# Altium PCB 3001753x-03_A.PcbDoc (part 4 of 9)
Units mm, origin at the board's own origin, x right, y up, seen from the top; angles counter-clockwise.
Board outline 210 x 130 mm, 8 copper layers (1-TOP, 2-GND, 3-INTOP, 4-PWR, 5-PWR, 6-INBOT, 7-GND, 8-BOTTOM), stack 1.646 mm thick; 676 components, 623 nets, 2861 pads, 2382 vias.
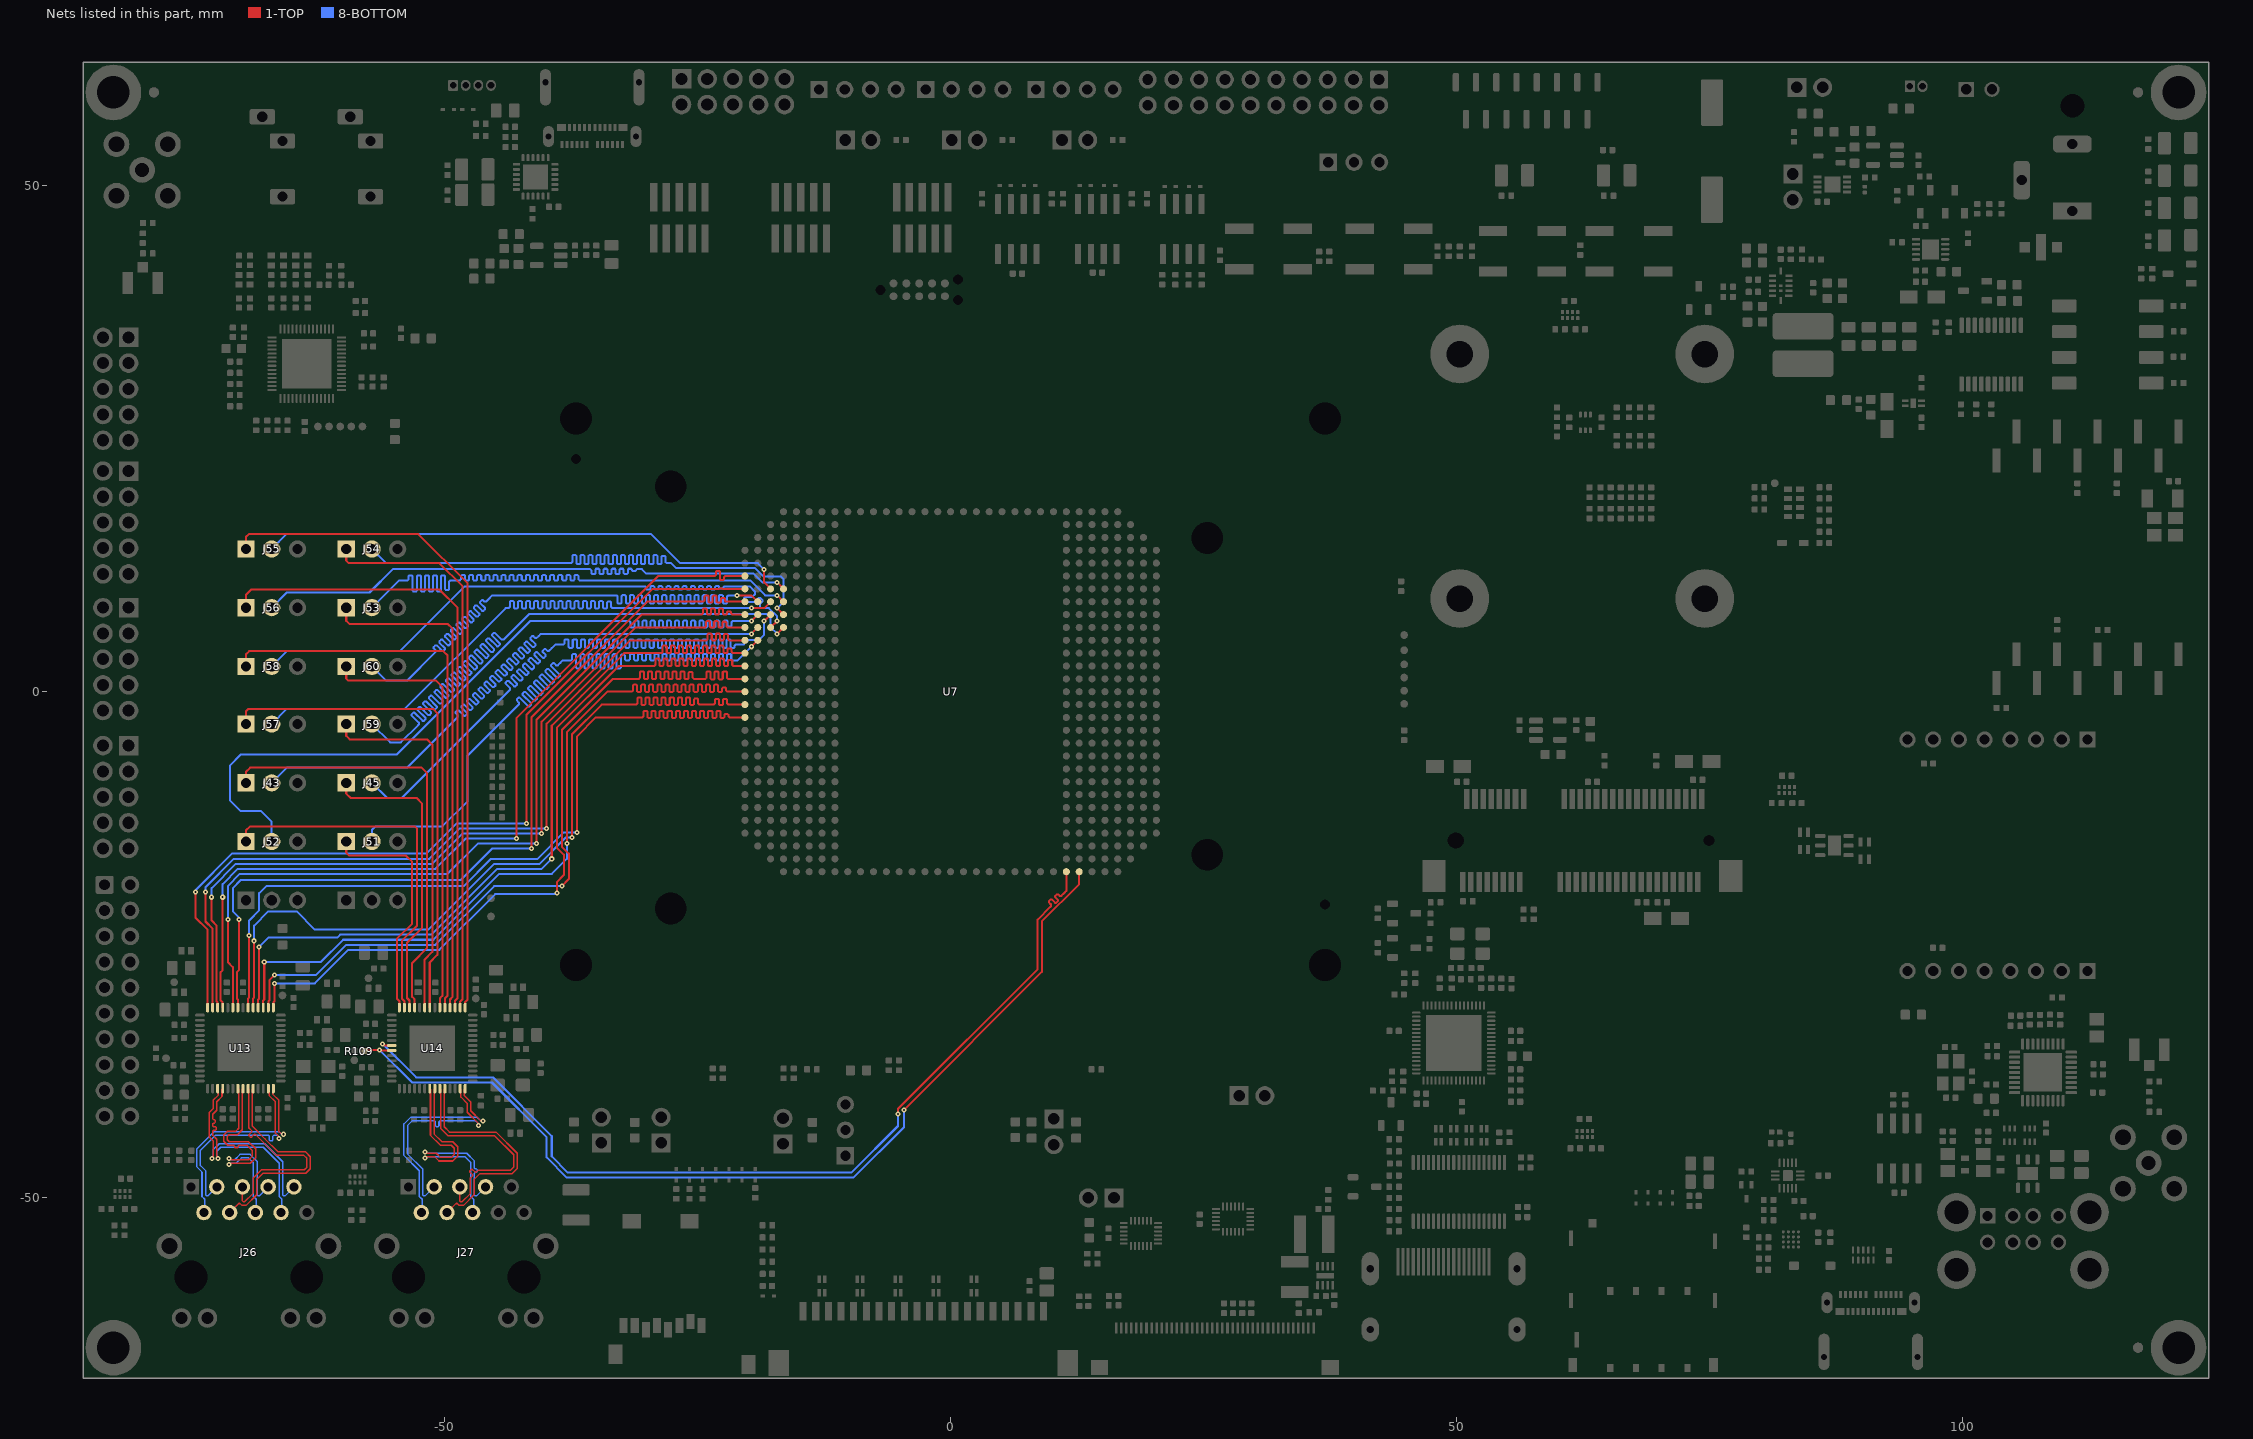
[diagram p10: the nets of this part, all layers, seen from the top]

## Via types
v1: diameter 0.5, hole 0.2, 1-TOP to 8-BOTTOM, 1547 vias
v2: diameter 0.68, hole 0.3, 1-TOP to 8-BOTTOM, 835 vias

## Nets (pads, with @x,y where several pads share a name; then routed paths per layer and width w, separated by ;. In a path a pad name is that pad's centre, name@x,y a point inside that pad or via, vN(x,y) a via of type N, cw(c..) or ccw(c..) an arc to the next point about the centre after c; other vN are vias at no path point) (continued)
ENET1_RD0: U7.A16 U13.44 | length 85
  1-TOP w0.2: U13.44@-67.4,-31.2 -67.4,-30.6 -67.3,-30.5 -67.3,-28.5 v1(-66.8,-28) ; v1(-38.4,-19.2) -37.7,-18.5 -37.7,-16 -38.4,-15.3 -38.4,-3.779 -33.351,1.27 -30.898,1.27 -30.798,1.27 -30.681,1.387 -30.681,1.927 -30.601,2.007 -30.361,2.007 -30.281,1.927 -30.281,1.315 -30.201,1.235 -29.961,1.235 -29.881,1.315 -29.881,1.927 -29.801,2.007 -29.561,2.007 -29.481,1.927 -29.481,1.315 -29.401,1.235 -29.161,1.235 -29.081,1.315 -29.081,1.927 -29.001,2.007 -28.761,2.007 -28.681,1.927 -28.681,1.315 -28.601,1.235 -28.361,1.235 -28.281,1.315 -28.281,1.927 -28.201,2.007 -27.961,2.007 -27.881,1.927 -27.881,1.315 -27.801,1.235 -27.561,1.235 -27.481,1.315 -27.481,1.927 -27.401,2.007 -27.161,2.007 -27.081,1.927 -27.081,1.315 -27.001,1.235 -26.761,1.235 -26.681,1.315 -26.681,1.927 -26.601,2.007 -26.361,2.007 -26.281,1.927 -26.281,1.315 -26.201,1.235 -25.961,1.235 -25.881,1.315 -25.881,1.871 -25.801,1.951 -25.561,1.951 -25.481,1.871 -25.481,1.387 -25.364,1.27 -24.8,1.27 -24.325,1.27 -24.225,1.27 -24.108,1.387 -24.108,1.937 -24.028,2.017 -23.788,2.017 -23.708,1.937 -23.708,1.301 -23.628,1.221 -23.388,1.221 -23.308,1.301 -23.308,1.937 -23.228,2.017 -22.988,2.017 -22.908,1.937 -22.908,1.301 -22.828,1.221 -22.588,1.221 -22.508,1.301 -22.508,1.937 -22.428,2.017 -22.188,2.017 -22.108,1.937 -22.108,1.387 -21.991,1.27 -21.375,1.27 U7.A16@-20.32,1.27
  8-BOTTOM w0.2: v1(-66.8,-28) -62.7,-28 -59.7,-25 -50.9,-25 -45.1,-19.2 v1(-38.4,-19.2)
ENET1_RD1: U7.A15 U13.45 | length 85
  1-TOP w0.2: U13.45@-67.9,-31.2 -67.9,-30.5 -67.8,-30.4 v1(-67.8,-26.7) ; v1(-37.9,-15) -37.9,-3.986 -33.914,0 -31.594,0 -31.494,0 -31.377,0.117 -31.377,0.628 -31.297,0.708 -31.057,0.708 -30.977,0.628 -30.977,0.057 -30.897,-0.023 -30.657,-0.023 -30.577,0.057 -30.577,0.628 -30.497,0.708 -30.257,0.708 -30.177,0.628 -30.177,0.057 -30.097,-0.023 -29.857,-0.023 -29.777,0.057 -29.777,0.628 -29.697,0.708 -29.457,0.708 -29.377,0.628 -29.377,0.057 -29.297,-0.023 -29.057,-0.023 -28.977,0.057 -28.977,0.628 -28.897,0.708 -28.657,0.708 -28.577,0.628 -28.577,0.057 -28.497,-0.023 -28.257,-0.023 -28.177,0.057 -28.177,0.628 -28.097,0.708 -27.857,0.708 -27.777,0.628 -27.777,0.057 -27.697,-0.023 -27.457,-0.023 -27.377,0.057 -27.377,0.628 -27.297,0.708 -27.057,0.708 -26.977,0.628 -26.977,0.057 -26.897,-0.023 -26.657,-0.023 -26.577,0.057 -26.577,0.628 -26.497,0.708 -26.257,0.708 -26.177,0.628 -26.177,0.057 -26.097,-0.023 -25.857,-0.023 -25.777,0.057 -25.777,0.628 -25.697,0.708 -25.457,0.708 -25.377,0.628 -25.377,0.057 -25.297,-0.023 -25.057,-0.023 -24.977,0.057 -24.977,0.628 -24.897,0.708 -24.657,0.708 -24.577,0.628 -24.577,0.057 -24.497,-0.023 -24.257,-0.023 -24.177,0.057 -24.177,0.628 -24.097,0.708 -23.857,0.708 -23.777,0.628 -23.777,0.057 -23.697,-0.023 -23.457,-0.023 -23.377,0.057 -23.377,0.628 -23.297,0.708 -23.057,0.708 -22.977,0.628 -22.977,0.057 -22.897,-0.023 -22.657,-0.023 -22.577,0.057 -22.577,0.33 -22.497,0.41 -22.257,0.41 -22.177,0.33 -22.177,0.117 -22.06,0 -21.638,0 U7.A15@-20.32,0
  8-BOTTOM w0.2: v1(-67.8,-26.7) -62.2,-26.7 -60,-24.5 -51.1,-24.5 -44.6,-18 -39.4,-18 -37.9,-16.5 v1(-37.9,-15)
ENET1_RD2: U7.A14 U13.47 | length 85
  1-TOP w0.2: U13.47@-68.9,-31.2 -68.9,-30.3 -68.8,-30.2 v1(-68.8,-24.6) ; v1(-37.4,-14.4) -37.4,-4.193 -34.477,-1.27 -31.162,-1.27 -31.062,-1.27 -30.944,-1.153 -30.944,-0.638 -30.864,-0.558 -30.624,-0.558 -30.544,-0.638 -30.544,-1.212 -30.464,-1.292 -30.224,-1.292 -30.144,-1.212 -30.144,-0.638 -30.064,-0.558 -29.824,-0.558 -29.744,-0.638 -29.744,-1.212 -29.664,-1.292 -29.425,-1.292 -29.345,-1.212 -29.345,-0.638 -29.265,-0.558 -29.025,-0.558 -28.945,-0.638 -28.945,-1.212 -28.865,-1.292 -28.625,-1.292 -28.545,-1.212 -28.545,-0.638 -28.465,-0.558 -28.225,-0.558 -28.145,-0.638 -28.145,-1.212 -28.065,-1.292 -27.825,-1.292 -27.745,-1.212 -27.745,-0.638 -27.665,-0.558 -27.425,-0.558 -27.345,-0.638 -27.345,-1.212 -27.265,-1.292 -27.025,-1.292 -26.945,-1.212 -26.945,-0.638 -26.865,-0.558 -26.625,-0.558 -26.545,-0.638 -26.545,-1.212 -26.465,-1.292 -26.225,-1.292 -26.145,-1.212 -26.145,-0.638 -26.065,-0.558 -25.825,-0.558 -25.745,-0.638 -25.745,-1.212 -25.665,-1.292 -25.425,-1.292 -25.345,-1.212 -25.345,-0.749 -25.265,-0.669 -25.025,-0.669 -24.945,-0.749 -24.945,-1.153 -24.827,-1.27 -24.176,-1.27 -23.506,-1.27 -23.406,-1.27 -23.289,-1.153 -23.289,-0.788 -23.209,-0.708 -22.969,-0.708 -22.889,-0.788 -22.889,-1.238 -22.809,-1.318 -22.569,-1.318 -22.489,-1.238 -22.489,-0.788 -22.409,-0.708 -22.169,-0.708 -22.089,-0.788 -22.089,-1.153 -21.971,-1.27 -21.325,-1.27 U7.A14@-20.32,-1.27
  8-BOTTOM w0.2: v1(-68.8,-24.6) -68.8,-23.1 -67.4,-21.7 -64.6,-21.7 -62.8,-23.5 -51.6,-23.5 -45.1,-17 -40.6,-17 -38,-14.4 v1(-37.4,-14.4)
ENET1_RD3: U7.A13 U13.48 | length 85
  1-TOP w0.2: U13.48@-69.4,-31.2 -69.4,-30.3 -69.3,-30.2 v1(-69.3,-24.1) ; v1(-36.9,-13.9) -36.9,-4.4 -35.04,-2.54 -30.561,-2.54 -30.461,-2.54 -30.343,-2.423 -30.343,-1.963 -30.263,-1.883 -30.023,-1.883 -29.943,-1.963 -29.943,-2.501 -29.863,-2.581 -29.623,-2.581 -29.543,-2.501 -29.543,-1.963 -29.463,-1.883 -29.223,-1.883 -29.143,-1.963 -29.143,-2.501 -29.063,-2.581 -28.823,-2.581 -28.743,-2.501 -28.743,-1.963 -28.663,-1.883 -28.423,-1.883 -28.343,-1.963 -28.343,-2.501 -28.263,-2.581 -28.023,-2.581 -27.943,-2.501 -27.943,-1.963 -27.863,-1.883 -27.623,-1.883 -27.543,-1.963 -27.543,-2.501 -27.463,-2.581 -27.223,-2.581 -27.143,-2.501 -27.143,-1.963 -27.063,-1.883 -26.823,-1.883 -26.743,-1.963 -26.743,-2.501 -26.663,-2.581 -26.423,-2.581 -26.343,-2.501 -26.343,-1.963 -26.263,-1.883 -26.023,-1.883 -25.943,-1.963 -25.943,-2.501 -25.863,-2.581 -25.623,-2.581 -25.543,-2.501 -25.543,-1.963 -25.463,-1.883 -25.223,-1.883 -25.143,-1.963 -25.143,-2.501 -25.063,-2.581 -24.823,-2.581 -24.743,-2.501 -24.743,-1.963 -24.663,-1.883 -24.423,-1.883 -24.343,-1.963 -24.343,-2.501 -24.263,-2.581 -24.023,-2.581 -23.943,-2.501 -23.943,-1.963 -23.863,-1.883 -23.623,-1.883 -23.543,-1.963 -23.543,-2.501 -23.463,-2.581 -23.223,-2.581 -23.143,-2.501 -23.143,-1.963 -23.063,-1.883 -22.823,-1.883 -22.743,-1.963 -22.743,-2.501 -22.663,-2.581 -22.423,-2.581 -22.343,-2.501 -22.343,-2.295 -22.263,-2.215 -22.023,-2.215 -21.943,-2.295 -21.943,-2.423 -21.826,-2.54 -21.55,-2.54 U7.A13@-20.32,-2.54
  8-BOTTOM w0.2: v1(-69.3,-24.1) -69.3,-22.6 -68.3,-21.6 -68.3,-19.9 -67.6,-19.2 -48.1,-19.2 -45.4,-16.5 -40.8,-16.5 -38.2,-13.9 v1(-36.9,-13.9)
ENET1_RX_CTL: U7.A17 U13.43 | length 85
  1-TOP w0.2: U13.43@-66.9,-31.2 -66.9,-30.7 -66.8,-30.6 v1(-66.8,-28.8) ; v1(-38.9,-19.9) -38.9,-18.8 -38.2,-18.1 -38.2,-16.1 -38.9,-15.4 -38.9,-3.572 -32.788,2.54 -29.386,2.54 -29.286,2.54 -29.169,2.657 -29.169,3.217 -29.089,3.297 -28.849,3.297 -28.769,3.217 -28.769,2.617 -28.689,2.537 -28.449,2.537 -28.369,2.617 -28.369,3.217 -28.289,3.297 -28.049,3.297 -27.969,3.217 -27.969,2.617 -27.889,2.537 -27.649,2.537 -27.569,2.617 -27.569,3.217 -27.489,3.297 -27.249,3.297 -27.169,3.217 -27.169,2.617 -27.089,2.537 -26.849,2.537 -26.769,2.617 -26.769,3.217 -26.689,3.297 -26.449,3.297 -26.369,3.217 -26.369,2.617 -26.289,2.537 -26.049,2.537 -25.969,2.617 -25.969,3.217 -25.889,3.297 -25.649,3.297 -25.569,3.217 -25.569,2.617 -25.489,2.537 -25.249,2.537 -25.169,2.617 -25.169,3.217 -25.089,3.297 -24.849,3.297 -24.769,3.217 -24.769,2.617 -24.689,2.537 -24.449,2.537 -24.369,2.617 -24.369,3.217 -24.289,3.297 -24.049,3.297 -23.969,3.217 -23.969,2.617 -23.889,2.537 -23.649,2.537 -23.569,2.617 -23.569,3.217 -23.489,3.297 -23.249,3.297 -23.169,3.217 -23.169,2.617 -23.089,2.537 -22.849,2.537 -22.769,2.617 -22.769,3.217 -22.689,3.297 -22.449,3.297 -22.369,3.217 -22.369,2.617 -22.289,2.537 -22.049,2.537 -21.969,2.617 -21.969,3.064 -21.889,3.144 -21.649,3.144 -21.569,3.064 -21.569,2.657 -21.452,2.54 -20.972,2.54 U7.A17@-20.32,2.54
  8-BOTTOM w0.2: v1(-66.8,-28.8) -62.8,-28.8 -59.5,-25.5 -50.5,-25.5 -45,-20 -39.167,-20 -39.125,-19.957 -38.957,-19.957 v1(-38.9,-19.9)
ENET1_RXC: U7.A18 U13.46 | length 85
  1-TOP w0.2: U13.46@-68.4,-31.2 -68.4,-30.4 -68.3,-30.3 v1(-68.3,-25.2) ; v1(-39.4,-16.5) -39.4,-3.35 -36.44,-0.39 -32.24,3.81 -28.656,3.81 -28.556,3.81 -28.439,3.927 -28.439,4.477 -28.359,4.557 -28.119,4.557 -28.039,4.477 -28.039,3.885 -27.959,3.805 -27.719,3.805 -27.639,3.885 -27.639,4.477 -27.559,4.557 -27.319,4.557 -27.239,4.477 -27.239,3.885 -27.159,3.805 -26.919,3.805 -26.839,3.885 -26.839,4.477 -26.759,4.557 -26.519,4.557 -26.439,4.477 -26.439,3.885 -26.359,3.805 -26.119,3.805 -26.039,3.885 -26.039,4.477 -25.959,4.557 -25.719,4.557 -25.639,4.477 -25.639,3.885 -25.559,3.805 -25.319,3.805 -25.239,3.885 -25.239,4.477 -25.159,4.557 -24.919,4.557 -24.839,4.477 -24.839,3.885 -24.759,3.805 -24.519,3.805 -24.439,3.885 -24.439,4.477 -24.359,4.557 -24.119,4.557 -24.039,4.477 -24.039,3.885 -23.959,3.805 -23.719,3.805 -23.639,3.885 -23.639,4.477 -23.559,4.557 -23.319,4.557 -23.239,4.477 -23.239,3.885 -23.159,3.805 -22.919,3.805 -22.839,3.885 -22.839,4.477 -22.759,4.557 -22.519,4.557 -22.439,4.477 -22.439,3.885 -22.359,3.805 -22.119,3.805 -22.039,3.885 -22.039,4.208 -21.959,4.288 -21.719,4.288 -21.639,4.208 -21.639,3.927 -21.522,3.81 -21.2,3.81 -21.1,3.81 U7.A18@-20.32,3.81
  8-BOTTOM w0.2: v1(-68.3,-25.2) -67.4,-24.3 -60.6,-24.3 -60.3,-24 -51.3,-24 -44.8,-17.5 -40.4,-17.5 v1(-39.4,-16.5)
ENET1_TD0: U7.A22 U13.50 | length 85
  1-TOP w0.2: U13.50@-70.4,-31.2 -70.4,-30.4 -70.5,-30.3 -70.5,-27.7 -70.3,-27.5 v1(-70.3,-22.5) ; v1(-41.4,-15.5) -41.4,-2.536 -29.974,8.89 -24.52,8.89 -24.42,8.89 -24.303,9.007 -24.303,9.419 -24.223,9.499 -23.983,9.499 -23.903,9.419 -23.903,8.878 -23.823,8.798 -23.583,8.798 -23.503,8.878 -23.503,9.419 -23.423,9.499 -23.183,9.499 -23.103,9.419 -23.103,8.878 -23.023,8.798 -22.783,8.798 -22.703,8.878 -22.703,9.188 -22.623,9.268 -22.383,9.268 -22.303,9.188 -22.303,9.007 -22.185,8.89 -21.7,8.89 U7.A22@-20.32,8.89
  8-BOTTOM w0.2: v1(-70.3,-22.5) -70.357,-22.443 -70.357,-22.243 -70.9,-21.7 -70.9,-19.4 -70.1,-18.6 -48.4,-18.6 -45.3,-15.5 v1(-41.4,-15.5)
ENET1_TD1: U7.A21 U13.51 | length 85
  1-TOP w0.2: v1(-71.4,-22.5) -71.4,-26.7 -70.9,-27.2 U13.51@-70.9,-31.2 ; v1(-40.9,-15) -40.9,-2.743 -37.057,1.1 -30.537,7.62 -24.699,7.62 -24.599,7.62 -24.482,7.737 -24.482,8.125 -24.402,8.205 -24.162,8.205 -24.082,8.125 -24.082,7.69 -24.002,7.61 -23.762,7.61 -23.682,7.69 -23.682,8.125 -23.602,8.205 -23.362,8.205 -23.282,8.125 -23.282,7.69 -23.202,7.61 -22.962,7.61 -22.882,7.69 -22.882,8.125 -22.802,8.205 -22.562,8.205 -22.482,8.125 -22.482,7.69 -22.402,7.61 -22.162,7.61 -22.082,7.69 -22.082,7.864 -22.002,7.944 -21.762,7.944 -21.682,7.864 -21.682,7.737 -21.565,7.62 -21.375,7.62 U7.A21@-20.32,7.62
  8-BOTTOM w0.2: v1(-71.4,-22.5) -71.4,-19.2 -70.2,-18 -49.7,-18 -46.7,-15 v1(-40.9,-15)
ENET1_TD2: U7.A20 U13.54 | length 85
  1-TOP w0.2: v1(-73,-20.3) -73,-22.6 -72.5,-23.1 -72.5,-30.6 -72.4,-30.7 U13.54@-72.4,-31.2 ; v1(-40.4,-14) -40.4,-2.95 -36.85,0.6 -31.1,6.35 -24.365,6.35 -24.265,6.35 -24.147,6.467 -24.147,6.901 -24.067,6.981 -23.827,6.981 -23.747,6.901 -23.747,6.407 -23.667,6.327 -23.427,6.327 -23.347,6.407 -23.347,6.901 -23.267,6.981 -23.027,6.981 -22.947,6.901 -22.947,6.407 -22.867,6.327 -22.627,6.327 -22.547,6.407 -22.547,6.833 -22.467,6.913 -22.227,6.913 -22.147,6.833 -22.147,6.467 -22.03,6.35 -21.375,6.35 U7.A20@-20.32,6.35
  8-BOTTOM w0.2: v1(-73,-20.3) -73,-19.4 -70.6,-17 -51.2,-17 -48.2,-14 v1(-40.4,-14)
ENET1_TD3: U7.A19 U13.55 | length 85
  1-TOP w0.2: v1(-73.6,-19.8) -73.6,-22.7 -72.9,-23.4 U13.55@-72.9,-31.2 ; v1(-39.9,-13.5) -39.9,-3.157 -36.643,0.1 -31.663,5.08 -24.211,5.08 -24.111,5.08 -23.994,5.197 -23.994,5.668 -23.914,5.748 -23.674,5.748 -23.594,5.668 -23.594,5.141 -23.514,5.061 -23.274,5.061 -23.194,5.141 -23.194,5.668 -23.114,5.748 -22.874,5.748 -22.794,5.668 -22.794,5.141 -22.714,5.061 -22.474,5.061 -22.394,5.141 -22.394,5.616 -22.314,5.696 -22.074,5.696 -21.994,5.616 -21.994,5.197 -21.877,5.08 -21.293,5.08 U7.A19@-20.32,5.08
  8-BOTTOM w0.2: v1(-73.6,-19.8) -73.6,-19.3 -70.8,-16.5 -51.5,-16.5 -48.5,-13.5 v1(-39.9,-13.5)
ENET1_TX_CTL: U7.A23 U13.56 | length 85
  1-TOP w0.2: v1(-74.6,-19.8) -74.6,-22.3 -73.4,-23.5 U13.56@-73.4,-31.2 ; v1(-41.9,-13) -41.9,-2.3 -29.44,10.16 -22.875,10.16 -22.825,10.21 -22.55,10.21 -22.5,10.16 U7.A23@-20.32,10.16
  8-BOTTOM w0.2: v1(-74.6,-19.8) -74.543,-19.743 -74.543,-19.543 -71,-16 -51.8,-16 -48.8,-13 v1(-41.9,-13)
ENET1_TXC: U7.A24 U13.53 | length 85
  1-TOP w0.2: U13.53@-71.9,-31.2 -71.9,-30.7 -72.1,-30.5 -72.1,-27.7 -71.9,-27.5 v1(-71.9,-20.3) ; v1(-42.9,-14.5) -42.9,-2.6 -28.87,11.43 -23.394,11.43 -23.294,11.43 -23.177,11.547 -23.177,11.85 -23.097,11.93 -22.857,11.93 -22.777,11.85 -22.777,11.107 -22.697,11.027 -22.457,11.027 -22.377,11.107 -22.377,11.313 -22.259,11.43 -21.559,11.43 U7.A24@-20.32,11.43
  8-BOTTOM w0.2: v1(-71.9,-20.3) -71.9,-19 -70.4,-17.5 -50.9,-17.5 -47.9,-14.5 v1(-42.9,-14.5)
ENET2_MDC: U7.AF1 U14.7 | length 93.9
  1-TOP w0.2: v1(-56.1,-34.8) -55.95,-34.95 U14.7@-55.2,-34.95 ; v1(-5.2,-41.7) -5.2,-41.2 8.595,-27.405 8.595,-22.505 9.849,-21.251 9.919,-21.181 9.919,-21.015 9.705,-20.801 9.705,-20.688 9.875,-20.518 9.988,-20.518 10.316,-20.846 10.429,-20.846 10.599,-20.677 10.599,-20.563 10.331,-20.295 10.331,-20.182 10.501,-20.012 10.614,-20.012 10.768,-20.166 10.934,-20.166 11.2,-19.9 11.43,-19.67 U7.AF1@11.43,-17.78
  8-BOTTOM w0.2: v1(-56.1,-34.8) -52.8,-38.1 -45.2,-38.1 -39.4,-43.9 -39.4,-45.9 -37.8,-47.5 -9.8,-47.5 -5.2,-42.9 v1(-5.2,-41.7)
ENET2_MDIO: R109.2 U7.AG1 U14.8 | length 95.4
  1-TOP w0.2: R109.2@-57.92,-35.5 -57.82,-35.4 v1(-56.4,-35.4) -56.35,-35.45 U14.8@-55.2,-35.45 ; v1(-4.6,-41.3) 9.019,-27.681 9.019,-22.681 12.7,-19 U7.AG1@12.7,-17.78
  8-BOTTOM w0.2: v1(-56.4,-35.4) -53.2,-38.6 -45.3,-38.6 -39.9,-44 -39.9,-46 -37.9,-48 -9.6,-48 -4.6,-43 v1(-4.6,-41.3)
ENET2_RD0: J54.1 U14.44 | length 55.4
  1-TOP w0.2: J54.1@-59.7,14.1 -59.7,12.94 -59.46,12.7 -50.5,12.7 -48.2,10.4 -48.2,-30.35 -48.45,-30.6 U14.44@-48.45,-31.2
ENET2_RD0/UART4_RX: J54.2 U7.D21 | length 64.7
  1-TOP w0.2: v1(-17.145,8.255) U7.D21@-16.51,7.62
  8-BOTTOM w0.2: J54.2@-57.16,14.1 -55.76,12.7 -37.588,12.7 -37.488,12.7 -37.371,12.817 -37.371,13.42 -37.291,13.5 -37.051,13.5 -36.971,13.42 -36.971,12.686 -36.891,12.606 -36.651,12.606 -36.571,12.686 -36.571,13.42 -36.491,13.5 -36.251,13.5 -36.171,13.42 -36.171,12.686 -36.091,12.606 -35.851,12.606 -35.771,12.686 -35.771,13.42 -35.691,13.5 -35.451,13.5 -35.371,13.42 -35.371,12.686 -35.291,12.606 -35.051,12.606 -34.971,12.686 -34.971,13.42 -34.891,13.5 -34.651,13.5 -34.571,13.42 -34.571,12.686 -34.491,12.606 -34.251,12.606 -34.171,12.686 -34.171,13.42 -34.091,13.5 -33.851,13.5 -33.771,13.42 -33.771,12.686 -33.691,12.606 -33.451,12.606 -33.371,12.686 -33.371,13.42 -33.291,13.5 -33.051,13.5 -32.971,13.42 -32.971,12.686 -32.891,12.606 -32.651,12.606 -32.571,12.686 -32.571,13.42 -32.491,13.5 -32.251,13.5 -32.171,13.42 -32.171,12.686 -32.091,12.606 -31.851,12.606 -31.771,12.686 -31.771,13.42 -31.691,13.5 -31.451,13.5 -31.371,13.42 -31.371,12.686 -31.291,12.606 -31.051,12.606 -30.971,12.686 -30.971,13.42 -30.891,13.5 -30.651,13.5 -30.571,13.42 -30.571,12.686 -30.491,12.606 -30.251,12.606 -30.171,12.686 -30.171,13.42 -30.091,13.5 -29.851,13.5 -29.771,13.42 -29.771,12.686 -29.691,12.606 -29.451,12.606 -29.371,12.686 -29.371,13.42 -29.291,13.5 -29.051,13.5 -28.971,13.42 -28.971,12.686 -28.891,12.606 -28.651,12.606 -28.571,12.686 -28.571,13.346 -28.491,13.426 -28.251,13.426 -28.171,13.346 -28.171,12.817 -28.054,12.7 -27.71,12.7 -27.6,12.7 -27.1,12.2 -19.3,12.2 -18.5,11.4 -16.8,11.4 -16.5,11.1 -16.5,8.9 v1(-17.145,8.255)
ENET2_RD1: J56.1 U14.45 | length 62.8
  1-TOP w0.2: J56.1@-69.6,8.3 -69.6,9.6 -69.1,10.1 -50.5,10.1 -48.7,8.3 -48.7,-30.25 -48.95,-30.5 U14.45@-48.95,-31.2
ENET2_RD1/GPIO4_IO25: J56.2 U7.D23 | length 57.4
  1-TOP w0.2: v1(-17.145,10.795) U7.D23@-16.51,10.16
  8-BOTTOM w0.2: J56.2@-67.06,8.3 -65.56,9.8 -57.4,9.8 -55.1,12.1 -36.107,12.1 -35.607,12.1 -35.49,11.983 -35.49,11.695 -35.41,11.615 -35.17,11.615 -35.09,11.695 -35.09,12.067 -35.01,12.147 -34.77,12.147 -34.69,12.067 -34.69,11.695 -34.61,11.615 -34.37,11.615 -34.29,11.695 -34.29,12.067 -34.21,12.147 -33.97,12.147 -33.89,12.067 -33.89,11.695 -33.81,11.615 -33.57,11.615 -33.49,11.695 -33.49,12.067 -33.41,12.147 -33.17,12.147 -33.09,12.067 -33.09,11.695 -33.01,11.615 -32.77,11.615 -32.69,11.695 -32.69,12.067 -32.61,12.147 -32.37,12.147 -32.29,12.067 -32.29,11.722 -32.21,11.642 -31.97,11.642 -31.89,11.722 -31.89,12.067 -31.81,12.147 -31.57,12.147 -31.49,12.067 -31.49,11.983 -31.41,11.903 -31.17,11.903 -31.09,11.983 -30.973,12.1 -30.592,12.1 -30.5,12.1 -30.1,11.7 -19.5,11.7 -18.595,10.795 v1(-17.145,10.795)
ENET2_RD2: J58.1 U14.47 | length 56.3
  1-TOP w0.2: J58.1@-69.6,2.5 -69.6,3.7 -69.3,4 -50.1,4 -49.7,3.6 -49.7,-30.05 -49.95,-30.3 U14.47@-49.95,-31.2
ENET2_RD2/UART4_CTS: J58.2 U7.C20 | length 63.9
  1-TOP w0.2: U7.C20@-17.78,6.35 v1(-17.145,6.985)
  8-BOTTOM w0.2: J58.2@-67.06,2.5 -65.56,4 -54.4,4 -48,10.4 -30.685,10.4 -30.185,10.4 -30.068,10.283 -30.068,10.172 -29.988,10.092 -29.748,10.092 -29.668,10.172 -29.668,10.35 -29.588,10.43 -29.348,10.43 -29.268,10.35 -29.268,10.172 -29.188,10.092 -28.948,10.092 -28.868,10.172 -28.868,10.35 -28.788,10.43 -28.548,10.43 -28.468,10.35 -28.468,10.172 -28.388,10.092 -28.148,10.092 -28.068,10.172 -28.068,10.35 -27.988,10.43 -27.748,10.43 -27.668,10.35 -27.668,10.172 -27.588,10.092 -27.348,10.092 -27.268,10.172 -27.268,10.35 -27.188,10.43 -26.948,10.43 -26.868,10.35 -26.868,10.172 -26.788,10.092 -26.548,10.092 -26.468,10.172 -26.468,10.35 -26.388,10.43 -26.148,10.43 -26.068,10.35 -26.068,10.172 -25.988,10.092 -25.748,10.092 -25.668,10.172 -25.668,10.35 -25.588,10.43 -25.348,10.43 -25.268,10.35 -25.268,10.172 -25.188,10.092 -24.948,10.092 -24.868,10.172 -24.868,10.35 -24.788,10.43 -24.548,10.43 -24.468,10.35 -24.468,10.172 -24.388,10.092 -24.148,10.092 -24.068,10.172 -24.068,10.35 -23.988,10.43 -23.748,10.43 -23.668,10.35 -23.668,10.173 -23.588,10.093 -23.348,10.093 -23.268,10.173 -23.268,10.35 -23.188,10.43 -22.948,10.43 -22.868,10.35 -22.868,10.283 -22.788,10.203 -22.548,10.203 -22.468,10.283 ; -22.468,10.283 -22.351,10.4 -21.975,10.4 -19.85,10.4 -19.325,9.875 -19.325,9.625 -19.575,9.375 -20.3,9.375 -20.425,9.25 -20.425,9.025 -20.275,8.875 -19.375,8.875 -19,9.25 -18.775,9.25 -18.6,9.075 -18.6,8.9 -18.85,8.65 -18.85,8.375 -18.725,8.25 -17.95,8.25 -17.145,7.445 v1(-17.145,6.985)
ENET2_RD3: J60.1 U14.48 | length 42.8
  1-TOP w0.2: J60.1@-59.7,2.5 -59.7,1.3 -59.5,1.1 -50.825,1.1 -50.2,0.475 -50.2,-30.05 -50.45,-30.3 U14.48@-50.45,-31.2
ENET2_RD3/GPIO4_IO27: J60.2 U7.B22 | length 77.3
  1-TOP w0.2: v1(-21.1,9.525) -19.685,9.525 U7.B22@-19.05,8.89
  8-BOTTOM w0.2: J60.2@-57.16,2.5 -55.76,1.1 -53.7,1.1 -50.938,3.862 -50.868,3.932 -50.868,4.098 -51.062,4.292 -51.062,4.405 -50.892,4.575 -50.779,4.575 -50.23,4.026 -50.116,4.026 -49.947,4.196 -49.947,4.309 -50.496,4.858 -50.496,4.971 -50.326,5.141 -50.213,5.141 -49.664,4.591 -49.551,4.591 -49.381,4.761 -49.381,4.874 -49.93,5.424 -49.93,5.537 -49.761,5.706 -49.647,5.706 -49.098,5.157 -48.985,5.157 -48.815,5.327 -48.815,5.44 -49.365,5.989 -49.365,6.102 -49.195,6.272 -49.082,6.272 -48.533,5.723 -48.419,5.723 -48.25,5.893 -48.25,6.006 -48.799,6.555 -48.799,6.668 -48.629,6.838 -48.516,6.838 -47.967,6.289 -47.854,6.289 -47.684,6.458 -47.684,6.571 -48.233,7.121 -48.233,7.234 -48.064,7.403 -47.95,7.403 -47.401,6.854 -47.288,6.854 -47.118,7.024 -47.118,7.137 -47.668,7.686 -47.668,7.799 -47.498,7.969 -47.385,7.969 -46.836,7.42 -46.722,7.42 -46.553,7.59 -46.553,7.703 -47.102,8.252 -47.102,8.365 -46.932,8.535 -46.819,8.535 -46.27,7.986 -46.157,7.986 -45.987,8.155 -45.987,8.268 -46.473,8.755 -46.473,8.868 -46.304,9.038 -46.19,9.038 -46.059,8.906 -45.894,8.906 -45.7,9.1 -45.275,9.525 -33.504,9.525 -33.004,9.525 -32.887,9.408 -32.887,8.775 -32.807,8.695 -32.567,8.695 -32.487,8.775 -32.487,9.456 -32.407,9.536 -32.167,9.536 -32.087,9.456 -32.087,8.775 -32.007,8.695 -31.767,8.695 -31.687,8.775 -31.687,9.456 -31.607,9.536 -31.367,9.536 -31.287,9.456 -31.287,8.775 -31.207,8.695 -30.967,8.695 -30.887,8.775 -30.887,9.456 -30.807,9.536 -30.567,9.536 -30.487,9.456 -30.487,8.775 -30.407,8.695 -30.167,8.695 -30.087,8.775 -30.087,9.456 -30.007,9.536 -29.767,9.536 -29.687,9.456 -29.687,8.775 -29.607,8.695 -29.367,8.695 -29.287,8.775 -29.287,9.456 -29.207,9.536 -28.967,9.536 -28.887,9.456 -28.887,8.775 -28.807,8.695 -28.567,8.695 -28.487,8.775 -28.487,9.456 -28.407,9.536 -28.167,9.536 -28.087,9.456 -28.087,8.775 -28.007,8.695 -27.767,8.695 -27.687,8.775 -27.687,9.456 -27.607,9.536 -27.367,9.536 -27.287,9.456 -27.287,8.775 -27.207,8.695 -26.967,8.695 -26.887,8.775 -26.887,9.456 -26.807,9.536 -26.567,9.536 -26.487,9.456 -26.487,8.775 -26.407,8.695 -26.167,8.695 -26.087,8.775 -26.087,9.456 -26.007,9.536 -25.767,9.536 -25.687,9.456 -25.687,8.775 -25.607,8.695 -25.367,8.695 -25.287,8.775 -25.287,9.456 -25.207,9.536 -24.967,9.536 -24.887,9.456 -24.887,8.775 -24.807,8.695 -24.567,8.695 -24.487,8.775 -24.487,9.456 -24.407,9.536 -24.167,9.536 -24.087,9.456 -24.087,8.775 -24.007,8.695 -23.767,8.695 -23.687,8.775 -23.687,9.456 -23.607,9.536 -23.367,9.536 -23.287,9.456 -23.287,8.775 -23.207,8.695 -22.967,8.695 -22.887,8.775 -22.887,9.456 -22.807,9.536 -22.567,9.536 -22.487,9.456 -22.487,8.775 -22.407,8.695 -22.167,8.695 -22.087,8.775 -22.087,9.408 -21.97,9.525 -21.709,9.525 v1(-21.1,9.525)
ENET2_RX_CTL: J55.1 U14.43 | length 67.2
  1-TOP w0.2: J55.1@-69.6,14.1 -69.6,15.3 -69.3,15.6 -52.6,15.6 ; -52.568,15.568 -47.7,10.7 -47.7,-30.4 -47.95,-30.65 U14.43@-47.95,-31.2
ENET2_RX_CTL/GPIO4_IO22: J55.2 U7.C23 | length 52.9
  1-TOP w0.2: v1(-18.415,12.065) -18.415,10.795 U7.C23@-17.78,10.16
  8-BOTTOM w0.2: J55.2@-67.06,14.1 -65.56,15.6 -29.6,15.6 -26.7,12.7 -19.05,12.7 v1(-18.415,12.065)
ENET2_RXC: J53.1 U14.46 | length 49.6
  1-TOP w0.2: J53.1@-59.7,8.3 -59.7,7 -59.4,6.7 -49.7,6.7 -49.2,6.2 -49.2,-30.15 -49.45,-30.4 U14.46@-49.45,-31.2
ENET2_RXC/GPIO4_IO23: J53.2 U7.D22 | length 70.5
  1-TOP w0.2: v1(-17.145,9.525) U7.D22@-16.51,8.89
  8-BOTTOM w0.2: J53.2@-57.16,8.3 -54.46,11 -53.75,11 -53.65,11 -53.533,11.117 -53.533,11.418 -53.453,11.498 -53.213,11.498 -53.133,11.418 -53.133,9.98 -53.053,9.9 -52.813,9.9 -52.733,9.98 -52.733,11.418 -52.653,11.498 -52.413,11.498 -52.333,11.418 -52.333,9.98 -52.253,9.9 -52.013,9.9 -51.933,9.98 -51.933,11.418 -51.853,11.498 -51.613,11.498 -51.533,11.418 -51.533,9.98 -51.453,9.9 -51.213,9.9 -51.133,9.98 -51.133,11.418 -51.053,11.498 -50.813,11.498 -50.733,11.418 -50.733,9.98 -50.653,9.9 -50.413,9.9 -50.333,9.98 -50.333,11.418 -50.253,11.498 -50.013,11.498 -49.933,11.418 -49.933,10.127 -49.853,10.047 -49.613,10.047 -49.533,10.127 -49.533,10.883 -49.416,11 -48.904,11 -48.581,11 -48.481,11 -48.364,11.117 -48.364,11.444 -48.284,11.524 -48.044,11.524 -47.964,11.444 -47.964,11.066 -47.884,10.986 -47.644,10.986 -47.564,11.066 -47.564,11.444 -47.484,11.524 -47.244,11.524 -47.164,11.444 -47.164,11.066 -47.084,10.986 -46.844,10.986 -46.764,11.066 -46.764,11.444 -46.684,11.524 -46.444,11.524 -46.364,11.444 -46.364,11.066 -46.284,10.986 -46.044,10.986 -45.964,11.066 -45.964,11.444 -45.884,11.524 -45.644,11.524 -45.564,11.444 -45.564,11.066 -45.484,10.986 -45.244,10.986 -45.164,11.066 -45.164,11.444 -45.084,11.524 -44.844,11.524 -44.764,11.444 -44.764,11.066 -44.684,10.986 -44.444,10.986 -44.364,11.066 -44.364,11.444 -44.284,11.524 -44.044,11.524 -43.964,11.444 -43.964,11.066 -43.884,10.986 -43.644,10.986 -43.564,11.066 -43.564,11.444 -43.484,11.524 -43.244,11.524 -43.164,11.444 -43.164,11.066 -43.084,10.986 -42.844,10.986 -42.764,11.066 -42.764,11.444 -42.684,11.524 -42.444,11.524 -42.364,11.444 -42.364,11.066 -42.284,10.986 -42.044,10.986 -41.964,11.066 -41.964,11.444 -41.884,11.524 -41.644,11.524 -41.564,11.444 -41.564,11.066 -41.484,10.986 -41.244,10.986 -41.164,11.066 -41.164,11.444 -41.084,11.524 -40.844,11.524 -40.764,11.444 -40.764,11.066 -40.684,10.986 -40.444,10.986 -40.364,11.066 -40.364,11.444 -40.284,11.524 -40.044,11.524 -39.964,11.444 -39.964,11.066 -39.884,10.986 -39.644,10.986 -39.564,11.066 -39.564,11.444 -39.484,11.524 -39.244,11.524 -39.164,11.444 -39.164,11.066 -39.084,10.986 -38.844,10.986 -38.764,11.066 -38.764,11.444 -38.684,11.524 -38.444,11.524 -38.364,11.444 -38.364,11.066 -38.284,10.986 -38.044,10.986 -37.964,11.066 -37.964,11.444 -37.884,11.524 -37.644,11.524 -37.564,11.444 -37.564,11.066 -37.484,10.986 -37.244,10.986 -37.164,11.066 -37.164,11.444 -37.084,11.524 -36.844,11.524 -36.764,11.444 -36.764,11.117 -36.647,11 -35.807,11 -19.8,11 -18.325,9.525 v1(-17.145,9.525)
ENET2_TD0: J57.1 U14.50 | length 49.7
  1-TOP w0.2: J57.1@-69.6,-3.1 -69.6,-1.946 -69.354,-1.7 -51.125,-1.7 -50.7,-2.125 -50.7,-26 -51.45,-26.75 U14.50@-51.45,-31.2
ENET2_TD0/UART4_TX: J57.2 U7.C22 | length 70.3
  1-TOP w0.2: v1(-19.685,8.255) -18.415,8.255 U7.C22@-17.78,8.89
  8-BOTTOM w0.2: J57.2@-67.06,-3.2 -65.56,-1.7 -53.9,-1.7 -43.945,8.255 -43.753,8.255 -43.653,8.255 -43.535,8.372 -43.535,8.869 -43.455,8.949 -43.215,8.949 -43.135,8.869 -43.135,8.311 -43.055,8.231 -42.815,8.231 -42.735,8.311 -42.735,8.869 -42.655,8.949 -42.415,8.949 -42.335,8.869 -42.335,8.311 -42.255,8.231 -42.015,8.231 -41.935,8.311 -41.935,8.869 -41.855,8.949 -41.615,8.949 -41.535,8.869 -41.535,8.311 -41.455,8.231 -41.215,8.231 -41.135,8.311 -41.135,8.869 -41.055,8.949 -40.815,8.949 -40.735,8.869 -40.735,8.311 -40.655,8.231 -40.415,8.231 -40.335,8.311 -40.335,8.869 -40.255,8.949 -40.015,8.949 -39.935,8.869 -39.935,8.311 -39.855,8.231 -39.615,8.231 -39.535,8.311 -39.535,8.869 -39.455,8.949 -39.215,8.949 -39.135,8.869 -39.135,8.311 -39.055,8.231 -38.815,8.231 -38.735,8.311 -38.735,8.869 -38.655,8.949 -38.415,8.949 -38.335,8.869 -38.335,8.311 -38.255,8.231 -38.015,8.231 -37.935,8.311 -37.935,8.869 -37.855,8.949 -37.615,8.949 -37.535,8.869 -37.535,8.311 -37.455,8.231 -37.215,8.231 -37.135,8.311 -37.135,8.869 -37.055,8.949 -36.815,8.949 -36.735,8.869 -36.735,8.311 -36.655,8.231 -36.415,8.231 -36.335,8.311 -36.335,8.869 -36.255,8.949 -36.015,8.949 -35.935,8.869 -35.935,8.311 -35.855,8.231 -35.615,8.231 -35.535,8.311 -35.535,8.869 -35.455,8.949 -35.215,8.949 -35.135,8.869 -35.135,8.311 -35.055,8.231 -34.815,8.231 -34.735,8.311 -34.735,8.869 -34.655,8.949 -34.415,8.949 -34.335,8.869 -34.335,8.311 -34.255,8.231 -34.015,8.231 -33.935,8.311 -33.935,8.825 -33.855,8.905 -33.615,8.905 -33.535,8.825 -33.535,8.372 -33.418,8.255 -33.099,8.255 v1(-19.685,8.255)
ENET2_TD1: J59.1 U14.51 | length 36.3
  1-TOP w0.2: J59.1@-59.7,-3.2 -59.7,-4.36 -59.36,-4.7 -51.725,-4.7 -51.2,-5.225 -51.2,-25.7 -51.95,-26.45 U14.51@-51.95,-31.2
ENET2_TD1/UART4_RTS: J59.2 U7.D20 | length 83.9
  1-TOP w0.2: v1(-17.145,5.715) U7.D20@-16.51,6.35
  8-BOTTOM w0.2: J59.2@-57.16,-3.2 -55.36,-5 -54.3,-5 -52.602,-3.302 -52.531,-3.231 -52.531,-3.065 -53.238,-2.358 -53.238,-2.245 -53.069,-2.075 -52.955,-2.075 -52.157,-2.873 -52.044,-2.873 -51.874,-2.703 -51.874,-2.59 -52.673,-1.792 -52.673,-1.679 -52.503,-1.509 -52.39,-1.509 -51.592,-2.307 -51.478,-2.307 -51.309,-2.138 -51.309,-2.025 -52.107,-1.226 -52.107,-1.113 -51.937,-0.944 -51.824,-0.944 -51.026,-1.742 -50.913,-1.742 -50.743,-1.572 -50.743,-1.459 -51.541,-0.661 -51.541,-0.548 -51.372,-0.378 -51.258,-0.378 -50.46,-1.176 -50.347,-1.176 -50.177,-1.006 -50.177,-0.893 -50.976,-0.095 -50.976,0.018 -50.806,0.188 -50.693,0.188 -49.895,-0.61 -49.781,-0.61 -49.612,-0.441 -49.612,-0.328 -50.41,0.471 -50.41,0.584 -50.24,0.753 -50.127,0.753 -49.329,-0.045 -49.216,-0.045 -49.046,0.125 -49.046,0.238 -49.844,1.036 -49.844,1.149 -49.675,1.319 -49.561,1.319 -48.763,0.521 -48.65,0.521 -48.48,0.691 -48.48,0.804 -49.279,1.602 -49.279,1.715 -49.109,1.885 -48.996,1.885 -48.198,1.087 -48.084,1.087 -47.915,1.256 -47.915,1.37 -48.713,2.168 -48.713,2.281 -48.543,2.451 -48.43,2.451 -47.632,1.652 -47.519,1.652 -47.349,1.822 -47.349,1.935 -48.147,2.733 -48.147,2.846 -47.977,3.016 -47.864,3.016 -47.066,2.218 -46.953,2.218 -46.783,2.388 -46.783,2.501 -47.581,3.299 -47.581,3.412 -47.412,3.582 -47.299,3.582 -46.5,2.784 -46.387,2.784 -46.218,2.953 -46.218,3.067 -47.016,3.865 -47.016,3.978 -46.846,4.148 -46.733,4.148 -45.935,3.349 -45.822,3.349 -45.652,3.519 -45.652,3.632 -46.45,4.43 -46.45,4.544 -46.28,4.713 -46.167,4.713 -45.369,3.915 -45.256,3.915 -45.086,4.085 -45.086,4.198 -45.884,4.996 -45.884,5.109 -45.715,5.279 -45.602,5.279 -44.803,4.481 -44.69,4.481 -44.521,4.65 -44.521,4.764 -45.298,5.541 -45.298,5.654 -45.128,5.823 -45.015,5.823 -44.328,5.137 -44.163,5.137 -44.041,5.259 -41.6,7.7 -18.2,7.7 -17.8,7.3 -17.8,6.37 v1(-17.145,5.715)
ENET2_TD2: J45.1 U14.54 | length 29.8
  1-TOP w0.2: J45.1@-59.7,-9 -59.7,-10.06 -59.26,-10.5 -52.75,-10.5 -52.2,-11.05 -52.2,-23.3 -53.7,-24.8 -53.7,-30.25 -53.45,-30.5 U14.54@-53.45,-31.2
ENET2_TD2/GPIO4_IO17: J45.2 U7.C21 | length 90.3
  1-TOP w0.2: v1(-18.415,6.985) U7.C21@-17.78,7.62
  8-BOTTOM w0.2: J45.2@-57.16,-9 -55.66,-10.5 -54.2,-10.5 -43.582,0.118 -43.511,0.189 -43.511,0.354 -43.955,0.798 -43.955,0.911 -43.785,1.081 -43.672,1.081 -43.115,0.524 -43.002,0.524 -42.833,0.694 -42.833,0.807 -43.389,1.363 -43.389,1.477 -43.219,1.646 -43.106,1.646 -42.55,1.09 -42.437,1.09 -42.267,1.259 -42.267,1.373 -42.823,1.929 -42.823,2.042 -42.654,2.212 -42.541,2.212 -41.984,1.655 -41.871,1.655 -41.701,1.825 -41.701,1.938 -42.258,2.495 -42.258,2.608 -42.088,2.778 -41.975,2.778 -41.418,2.221 -41.305,2.221 -41.136,2.391 -41.136,2.504 -41.692,3.06 -41.692,3.174 -41.522,3.343 -41.409,3.343 -40.853,2.787 -40.74,2.787 -40.57,2.956 -40.57,3.07 -41.126,3.626 -41.126,3.739 -40.957,3.909 -40.844,3.909 -40.287,3.352 -40.174,3.352 -40.004,3.522 -40.004,3.635 -40.292,3.923 -40.292,4.036 -40.123,4.206 -40.009,4.206 -39.834,4.031 -39.669,4.031 -39.4,4.3 -39.025,4.675 -38.342,4.675 -38.242,4.675 -38.125,4.792 -38.125,5.095 -38.045,5.175 -37.805,5.175 -37.725,5.095 -37.725,4.417 -37.645,4.337 -37.405,4.337 -37.325,4.417 -37.325,5.095 -37.245,5.175 -37.005,5.175 -36.925,5.095 -36.925,4.417 -36.845,4.337 -36.605,4.337 -36.525,4.417 -36.525,5.095 -36.445,5.175 -36.205,5.175 -36.125,5.095 -36.125,4.417 -36.045,4.337 -35.805,4.337 -35.725,4.417 -35.725,5.095 -35.645,5.175 -35.405,5.175 -35.325,5.095 -35.325,4.417 -35.245,4.337 -35.005,4.337 -34.925,4.417 -34.925,5.095 -34.845,5.175 -34.605,5.175 -34.525,5.095 -34.525,4.417 -34.445,4.337 -34.205,4.337 -34.125,4.417 -34.125,5.095 -34.045,5.175 -33.805,5.175 -33.725,5.095 -33.725,4.417 -33.645,4.337 -33.405,4.337 -33.325,4.417 -33.325,5.095 -33.245,5.175 -33.005,5.175 -32.925,5.095 -32.925,4.417 -32.845,4.337 -32.605,4.337 -32.525,4.417 -32.525,5.095 -32.445,5.175 -32.205,5.175 -32.125,5.095 -32.125,4.417 -32.045,4.337 -31.805,4.337 -31.725,4.417 -31.725,5.095 -31.645,5.175 -31.405,5.175 -31.325,5.095 -31.325,4.417 -31.245,4.337 -31.005,4.337 -30.925,4.417 -30.925,5.095 -30.845,5.175 -30.605,5.175 -30.525,5.095 -30.525,4.417 -30.445,4.337 -30.205,4.337 -30.125,4.417 -30.125,5.095 -30.045,5.175 -29.805,5.175 -29.725,5.095 -29.725,4.417 -29.645,4.337 -29.405,4.337 -29.325,4.417 -29.325,5.095 -29.245,5.175 -29.005,5.175 -28.925,5.095 -28.925,4.417 -28.845,4.337 -28.605,4.337 -28.525,4.417 -28.525,5.095 -28.445,5.175 -28.205,5.175 -28.125,5.095 -28.125,4.417 -28.045,4.337 -27.805,4.337 -27.725,4.417 -27.725,5.095 -27.645,5.175 -27.405,5.175 -27.325,5.095 -27.325,4.417 -27.245,4.337 -27.005,4.337 -26.925,4.417 -26.925,5.095 -26.845,5.175 -26.605,5.175 -26.525,5.095 -26.525,4.417 -26.445,4.337 -26.205,4.337 -26.125,4.417 -26.125,5.095 -26.045,5.175 -25.805,5.175 -25.725,5.095 -25.725,4.417 -25.645,4.337 -25.405,4.337 -25.325,4.417 -25.325,5.095 -25.245,5.175 -25.005,5.175 -24.925,5.095 -24.925,4.417 -24.845,4.337 -24.605,4.337 -24.525,4.417 -24.525,5.095 -24.445,5.175 -24.205,5.175 -24.125,5.095 -24.125,4.417 -24.045,4.337 -23.805,4.337 -23.725,4.417 -23.725,5.095 -23.645,5.175 -23.405,5.175 -23.325,5.095 -23.325,4.417 -23.245,4.337 -23.005,4.337 -22.925,4.417 -22.925,5.095 -22.845,5.175 -22.605,5.175 -22.525,5.095 -22.525,4.417 -22.445,4.337 -22.205,4.337 -22.125,4.417 -22.125,5.095 -22.045,5.175 -21.805,5.175 -21.725,5.095 -21.725,4.417 -21.645,4.337 -21.405,4.337 -21.325,4.417 -21.325,4.558 -21.208,4.675 -21.068,4.675 -20.425,4.675 -20,5.1 -18.95,5.1 -18.415,5.635 v1(-18.415,6.985)
ENET2_TD3: J52.1 U14.55 | length 36.7
  1-TOP w0.2: J52.1@-69.6,-14.8 -69.6,-13.7 -69.2,-13.3 -52.925,-13.3 -52.7,-13.525 -52.7,-23.093 -54.2,-24.593 -54.2,-30.3 -53.95,-30.55 U14.55@-53.95,-31.2
ENET2_TD3/GPIO4_IO16: J52.2 U7.B21 | length 83.5
  1-TOP w0.2: v1(-19.685,6.985) U7.B21@-19.05,7.62
  8-BOTTOM w0.2: J52.2@-67.06,-14.8 -67.06,-12.84 -68.1,-11.8 -70.1,-11.8 -71.2,-10.7 -71.2,-7.3 -70.1,-6.2 -54.7,-6.2 -41.515,6.985 -32.243,6.985 -31.743,6.985 -31.626,6.868 -31.626,6.428 -31.546,6.348 -31.306,6.348 -31.226,6.428 -31.226,6.944 -31.146,7.024 -30.906,7.024 -30.826,6.944 -30.826,6.428 -30.746,6.348 -30.506,6.348 -30.426,6.428 -30.426,6.944 -30.346,7.024 -30.106,7.024 -30.026,6.944 -30.026,6.428 -29.946,6.348 -29.706,6.348 -29.626,6.428 -29.626,6.944 -29.546,7.024 -29.306,7.024 -29.226,6.944 -29.226,6.428 -29.146,6.348 -28.906,6.348 -28.826,6.428 -28.826,6.944 -28.746,7.024 -28.506,7.024 -28.426,6.944 -28.426,6.428 -28.346,6.348 -28.106,6.348 -28.026,6.428 -28.026,6.944 -27.946,7.024 -27.706,7.024 -27.626,6.944 -27.626,6.428 -27.546,6.348 -27.306,6.348 -27.226,6.428 -27.226,6.944 -27.146,7.024 -26.906,7.024 -26.826,6.944 -26.826,6.428 -26.746,6.348 -26.506,6.348 -26.426,6.428 -26.426,6.944 -26.346,7.024 -26.106,7.024 -26.026,6.944 -26.026,6.428 -25.946,6.348 -25.706,6.348 -25.626,6.428 -25.626,6.944 -25.546,7.024 -25.306,7.024 -25.226,6.944 -25.226,6.428 -25.146,6.348 -24.906,6.348 -24.826,6.428 -24.826,6.944 -24.746,7.024 -24.506,7.024 -24.426,6.944 -24.426,6.428 -24.346,6.348 -24.106,6.348 -24.026,6.428 -24.026,6.944 -23.946,7.024 -23.706,7.024 -23.626,6.944 -23.626,6.428 -23.546,6.348 -23.306,6.348 -23.226,6.428 -23.226,6.944 -23.146,7.024 -22.906,7.024 -22.826,6.944 -22.826,6.428 -22.746,6.348 -22.506,6.348 -22.426,6.428 -22.426,6.944 -22.346,7.024 -22.106,7.024 -22.026,6.944 -22.026,6.537 -21.946,6.457 -21.706,6.457 -21.626,6.537 -21.626,6.868 -21.509,6.985 -21.107,6.985 v1(-19.685,6.985)
ENET2_TX_CTL: J51.1 U14.56 | length 23.1
  1-TOP w0.2: J51.1@-59.7,-14.8 -59.7,-15.9 -59.4,-16.2 -53.8,-16.2 -53.2,-16.8 -53.2,-22.9 -54.7,-24.4 -54.7,-30.3 -54.45,-30.55 U14.56@-54.45,-31.2
ENET2_TX_CTL/GPIO4_IO20: J51.2 U7.B19 | length 97.1
  1-TOP w0.2: v1(-19.685,4.445) U7.B19@-19.05,5.08
  8-BOTTOM w0.2: J51.2@-57.16,-14.8 -57.16,-13.66 -56.8,-13.3 -50.2,-13.3 -47.7,-10.8 -47.7,-6.3 -42.711,-1.311 -42.64,-1.24 -42.64,-1.074 -42.854,-0.86 -42.854,-0.747 -42.684,-0.577 -42.571,-0.577 -41.711,-1.438 -41.597,-1.438 -41.428,-1.268 -41.428,-1.155 -42.288,-0.294 -42.288,-0.181 -42.119,-0.012 -42.006,-0.012 -41.145,-0.872 -41.032,-0.872 -40.862,-0.703 -40.862,-0.59 -41.723,0.271 -41.723,0.384 -41.553,0.554 -41.44,0.554 -40.579,-0.307 -40.466,-0.307 -40.296,-0.137 -40.296,-0.024 -41.157,0.837 -41.157,0.95 -40.987,1.12 -40.874,1.12 -40.013,0.259 -39.9,0.259 -39.731,0.429 -39.731,0.542 -40.591,1.403 -40.591,1.516 -40.422,1.685 -40.309,1.685 -39.448,0.825 -39.335,0.825 -39.165,0.994 -39.165,1.108 -40.026,1.968 -40.026,2.081 -39.856,2.251 -39.743,2.251 -38.882,1.39 -38.769,1.39 -38.599,1.56 -38.599,1.673 -39.46,2.534 -39.46,2.647 -39.29,2.817 -39.177,2.817 -38.963,2.603 -38.797,2.603 -38.55,2.85 -38.3,3.1 -37.599,3.1 -37.499,3.1 -37.382,3.217 -37.382,3.638 -37.302,3.718 -37.062,3.718 -36.982,3.638 -36.982,2.38 -36.902,2.3 -36.662,2.3 -36.582,2.38 -36.582,3.638 -36.502,3.718 -36.262,3.718 -36.182,3.638 -36.182,2.38 -36.102,2.3 -35.862,2.3 -35.782,2.38 -35.782,3.638 -35.702,3.718 -35.462,3.718 -35.382,3.638 -35.382,2.38 -35.302,2.3 -35.062,2.3 -34.982,2.38 -34.982,3.638 -34.902,3.718 -34.662,3.718 -34.582,3.638 -34.582,2.38 -34.502,2.3 -34.262,2.3 -34.182,2.38 -34.182,3.638 -34.102,3.718 -33.862,3.718 -33.782,3.638 -33.782,2.38 -33.702,2.3 -33.462,2.3 -33.382,2.38 -33.382,3.638 -33.302,3.718 -33.062,3.718 -32.982,3.638 -32.982,2.38 -32.902,2.3 -32.662,2.3 -32.582,2.38 -32.582,3.591 -32.502,3.671 -32.262,3.671 -32.182,3.591 -32.182,3.217 -32.065,3.1 -31.909,3.1 -31.886,3.1 -31.786,3.1 -31.669,3.217 -31.669,3.665 -31.589,3.745 -31.349,3.745 -31.269,3.665 -31.269,3.174 -31.189,3.094 -30.949,3.094 -30.869,3.174 -30.869,3.665 -30.789,3.745 -30.549,3.745 -30.469,3.665 -30.469,3.174 -30.389,3.094 -30.149,3.094 -30.069,3.174 -30.069,3.665 -29.989,3.745 -29.749,3.745 -29.669,3.665 -29.669,3.174 -29.589,3.094 -29.349,3.094 -29.269,3.174 -29.269,3.665 -29.189,3.745 -28.949,3.745 -28.869,3.665 -28.869,3.174 -28.789,3.094 -28.549,3.094 -28.469,3.174 -28.469,3.665 -28.389,3.745 -28.149,3.745 -28.069,3.665 -28.069,3.174 -27.989,3.094 -27.749,3.094 -27.669,3.174 -27.669,3.665 -27.589,3.745 -27.349,3.745 -27.269,3.665 -27.269,3.174 -27.189,3.094 -26.949,3.094 -26.869,3.174 -26.869,3.665 -26.789,3.745 -26.549,3.745 -26.469,3.665 -26.469,3.174 -26.389,3.094 -26.149,3.094 -26.069,3.174 -26.069,3.665 -25.989,3.745 -25.749,3.745 -25.669,3.665 -25.669,3.174 -25.589,3.094 -25.349,3.094 -25.269,3.174 -25.269,3.665 -25.189,3.745 -24.949,3.745 -24.869,3.665 -24.869,3.174 -24.789,3.094 -24.549,3.094 -24.469,3.174 -24.469,3.665 -24.389,3.745 -24.149,3.745 -24.069,3.665 -24.069,3.174 -23.989,3.094 -23.749,3.094 -23.669,3.174 -23.669,3.665 -23.589,3.745 -23.349,3.745 -23.269,3.665 -23.269,3.174 -23.189,3.094 -22.949,3.094 -22.869,3.174 -22.869,3.665 -22.789,3.745 -22.549,3.745 -22.469,3.665 -22.469,3.174 -22.389,3.094 -22.149,3.094 -22.069,3.174 -22.069,3.665 -21.989,3.745 -21.749,3.745 -21.669,3.665 -21.669,3.217 -21.552,3.1 -21.299,3.1 -21.03,3.1 v1(-19.685,4.445)
ENET2_TXC: J43.1 U14.53 | length 43.3
  1-TOP w0.2: J43.1@-69.6,-9 -69.6,-7.9 -69.2,-7.5 -52.25,-7.5 -51.7,-8.05 -51.7,-25.3 -53.2,-26.8 -53.2,-30.15 -52.95,-30.4 U14.53@-52.95,-31.2
ENET2_TXC/GPIO4_IO21: J43.2 U7.B20 | length 76.9
  1-TOP w0.2: v1(-19.685,5.715) U7.B20@-19.05,6.35
  8-BOTTOM w0.2: J43.2@-67.06,-9 -65.56,-7.5 -53.7,-7.5 -48.758,-2.558 -48.688,-2.488 -48.688,-2.322 -48.894,-2.115 -48.894,-2.002 -48.725,-1.832 -48.611,-1.832 -48.064,-2.38 -47.951,-2.38 -47.781,-2.21 -47.781,-2.097 -48.329,-1.55 -48.329,-1.436 -48.159,-1.267 -48.046,-1.267 -47.498,-1.814 -47.385,-1.814 -47.215,-1.645 -47.215,-1.531 -47.763,-0.984 -47.763,-0.871 -47.593,-0.701 -47.48,-0.701 -46.933,-1.249 -46.819,-1.249 -46.65,-1.079 -46.65,-0.966 -47.197,-0.418 -47.197,-0.305 -47.028,-0.135 -46.914,-0.135 -46.367,-0.683 -46.254,-0.683 -46.084,-0.513 -46.084,-0.4 -46.632,0.147 -46.632,0.261 -46.462,0.43 -46.349,0.43 -45.801,-0.117 -45.688,-0.117 -45.518,0.052 -45.518,0.166 -46.066,0.713 -46.066,0.826 -45.896,0.996 -45.783,0.996 -45.235,0.448 -45.122,0.448 -44.953,0.618 -44.953,0.731 -45.5,1.279 -45.5,1.392 -45.33,1.562 -45.217,1.562 -44.67,1.014 -44.557,1.014 -44.387,1.184 -44.387,1.297 -44.934,1.844 -44.934,1.958 -44.765,2.127 -44.652,2.127 -44.104,1.58 -43.991,1.58 -43.821,1.749 -43.821,1.863 -44.369,2.41 -44.369,2.523 -44.199,2.693 -44.086,2.693 -43.538,2.145 -43.425,2.145 -43.256,2.315 -43.256,2.428 -43.803,2.976 -43.803,3.089 -43.633,3.259 -43.52,3.259 -42.973,2.711 -42.86,2.711 -42.69,2.881 -42.69,2.994 -43.237,3.542 -43.237,3.655 -43.068,3.824 -42.955,3.824 -42.407,3.277 -42.294,3.277 -42.124,3.447 -42.124,3.56 -42.672,4.107 -42.672,4.22 -42.502,4.39 -42.389,4.39 -41.841,3.843 -41.728,3.843 -41.559,4.012 -41.559,4.125 -42.106,4.673 -42.106,4.786 -41.936,4.956 -41.823,4.956 -41.276,4.408 -41.163,4.408 -40.993,4.578 -40.993,4.691 -41.51,5.209 -41.51,5.322 -41.341,5.491 -41.228,5.491 -41.051,5.315 -40.885,5.315 -40.7,5.5 -40.485,5.715 v1(-19.685,5.715)
ETH1_TXRXA_N: J26.3 U13.27 | length 21.1
  1-TOP w0.15: U13.27@-67.4,-39.2 -67.327,-39.273 -67.327,-39.874 -66.7,-40.501 -66.7,-43.6 -66.3,-44 -66.3,-44.1 v1(-66.337,-44.137)
  8-BOTTOM w0.15: J26.3@-72.49,-48.91 -73.382,-49.802 -73.506,-49.802 -73.594,-49.714 -73.594,-47.305 -74.1,-46.799 -74.1,-45.301 -72.599,-43.8 -67.8,-43.8 -67.375,-43.8 -67.287,-43.888 -67.287,-44.289 -67.217,-44.359 -67.007,-44.359 -66.937,-44.289 -66.937,-43.888 -66.849,-43.8 -66.6,-43.8 -66.5,-43.8 -66.337,-43.963 v1(-66.337,-44.137)
ETH1_TXRXA_P: J26.2 U13.28 | length 21
  1-TOP w0.15: U13.28@-66.9,-39.2 -66.973,-39.273 -66.973,-39.727 -66.346,-40.354 -66.346,-43.453 -66.05,-43.75 -65.95,-43.75 v1(-65.913,-43.713)
  8-BOTTOM w0.15: J26.2@-73.671,-51.361 -73.671,-50.138 -73.948,-49.861 -73.948,-47.452 -74.454,-46.946 -74.454,-45.154 -72.746,-43.446 -67.447,-43.446 -66.353,-43.446 -66.087,-43.713 v1(-65.913,-43.713)
ETH1_TXRXB_N: J26.5 U13.23 | length 22.7
  1-TOP w0.15: J26.5@-69.95,-48.91 -69.95,-50.302 -69.862,-50.39 -69.738,-50.39 -68.9,-49.552 -68.9,-48.049 -68.072,-47.221 -63.841,-47.221 -63.604,-46.984 -63.604,-46.072 -63.876,-45.8 -66.601,-45.8 -68.505,-43.896 -68.673,-43.727 -68.798,-43.727 -69.06,-43.989 -69.159,-43.989 -69.307,-43.841 -69.307,-43.742 -69.045,-43.48 -69.045,-43.356 -69.327,-43.074 -69.327,-43.037 -69.327,-39.273 U13.23@-69.4,-39.2
ETH1_TXRXB_P: J26.4 U13.24 | length 22.7
  1-TOP w0.15: J26.4@-71.22,-51.45 -70.323,-50.553 -70.199,-50.553 -70.009,-50.744 -69.591,-50.744 -68.546,-49.698 -68.546,-48.196 -67.925,-47.575 -63.695,-47.575 -63.25,-47.13 -63.25,-45.925 -63.729,-45.446 -66.454,-45.446 -67.725,-44.175 -68.973,-42.927 -68.973,-39.273 U13.24@-68.9,-39.2
ETH1_TXRXC_N: J26.7 U13.21 | length 21.1
  1-TOP w0.15: v1(-71.3,-46.1) -71.177,-46.223 -69.323,-46.223 -69,-45.9 -69,-45.3 -69.5,-44.8 -70.219,-44.8 -70.294,-44.8 -70.382,-44.888 -70.382,-44.996 -70.452,-45.066 -70.662,-45.066 -70.732,-44.996 -70.732,-44.888 -70.82,-44.8 -71.1,-44.8 -71.4,-44.8 -71.8,-44.4 -71.8,-43.799 -71.401,-43.4 -70.6,-43.4 -70.327,-43.127 -70.327,-39.273 U13.21@-70.4,-39.2
  8-BOTTOM w0.15: v1(-71.3,-46.1) -71.177,-46.223 -70.724,-46.223 -70.201,-45.7 -69.199,-45.7 -68.514,-46.385 -68.514,-47.815 -68.514,-49.714 -68.426,-49.802 -68.302,-49.802 J26.7@-67.41,-48.91
ETH1_TXRXC_P: J26.6 U13.22 | length 21.1
  1-TOP w0.15: v1(-71.3,-46.7) -71.177,-46.577 -70.33,-46.577 ; -70.477,-46.577 -69.176,-46.577 -68.646,-46.047 -68.646,-45.153 -69.353,-44.446 -71.253,-44.446 -71.446,-44.253 -71.446,-43.946 -71.254,-43.754 -70.453,-43.754 -69.973,-43.274 -69.973,-39.273 U13.22@-69.9,-39.2
  8-BOTTOM w0.15: v1(-71.3,-46.7) -71.177,-46.577 -70.577,-46.577 -70.054,-46.054 -69.346,-46.054 -68.868,-46.532 -68.868,-47.668 -68.868,-49.861 -68.591,-50.138 J26.6@-68.591,-51.361
ETH1_TXRXD_N: J26.9 U13.17 | length 21.1
  1-TOP w0.15: v1(-72.977,-46.1) -72.854,-45.977 -72.854,-44.346 -73.25,-43.95 -73.25,-41.599 -72.854,-41.203 -72.854,-40.353 -72.327,-39.826 -72.327,-39.273 U13.17@-72.4,-39.2
  8-BOTTOM w0.15: v1(-72.977,-46.1) -72.854,-45.977 -72.854,-45.253 -72.247,-44.646 -67.754,-44.646 -65.974,-46.426 -65.974,-49.714 -65.886,-49.802 -65.762,-49.802 J26.9@-64.87,-48.91
ETH1_TXRXD_P: J26.8 U13.18 | length 21
  1-TOP w0.15: v1(-72.377,-46.1) -72.5,-45.977 -72.5,-44.2 -72.871,-43.828 -72.896,-43.803 -72.896,-43.403 -72.808,-43.315 -72.621,-43.315 -72.551,-43.245 -72.551,-43.035 -72.621,-42.965 -72.826,-42.965 -72.896,-42.895 -72.896,-42.685 -72.826,-42.615 -72.724,-42.615 -72.654,-42.545 -72.654,-42.335 -72.724,-42.265 -72.808,-42.265 -72.896,-42.178 -72.896,-41.857 -72.896,-41.746 -72.5,-41.35 -72.5,-40.5 -71.973,-39.973 -71.973,-39.273 U13.18@-71.9,-39.2
  8-BOTTOM w0.15: v1(-72.377,-46.1) -72.5,-45.977 -72.5,-45.4 -72.1,-45 -67.901,-45 -66.328,-46.573 -66.328,-49.861 -66.051,-50.138 J26.8@-66.051,-51.361
ETH2_TXRXA_N: J27.3 U14.27 | length 21.8
  1-TOP w0.15: U14.27@-48.45,-39.2 -48.377,-39.273 -48.377,-40.047 -47.754,-40.67 -47.754,-41.546 -46.637,-42.663 v1(-46.637,-42.837)
  8-BOTTOM w0.15: J27.3@-51.02,-48.91 -51.912,-49.802 -52.036,-49.802 -52.124,-49.714 -52.124,-47.175 -53.646,-45.653 -53.646,-42.847 -53.199,-42.4 -51.4,-42.4 -50.975,-42.4 -50.887,-42.488 -50.887,-42.88 -50.817,-42.95 -50.607,-42.95 -50.537,-42.88 -50.537,-42.488 -50.449,-42.4 -50.1,-42.4 -47.4,-42.4 -46.9,-42.4 -46.637,-42.663 v1(-46.637,-42.837)
ETH2_TXRXA_P: J27.2 U14.28 | length 21.7
  1-TOP w0.15: U14.28@-47.95,-39.2 -48.023,-39.273 -48.023,-39.9 -47.4,-40.523 -47.4,-41.399 -46.45,-42.35 -46.387,-42.413 v1(-46.213,-42.413)
  8-BOTTOM w0.15: J27.2@-52.201,-51.361 -52.201,-50.138 -52.478,-49.861 -52.478,-47.322 -54,-45.8 -54,-42.7 -53.346,-42.046 -46.753,-42.046 -46.387,-42.413 v1(-46.213,-42.413)
ETH2_TXRXB_N: J27.5 U14.23 | length 23.4
  1-TOP w0.15: U14.23@-50.45,-39.2 -50.377,-39.273 -50.377,-43.123 -49.646,-43.854 -45.047,-43.854 -43.154,-45.747 -43.154,-46.953 -43.447,-47.246 -46.285,-47.246 -46.647,-47.246 -46.854,-47.454 -46.979,-47.454 -47.242,-47.19 -47.341,-47.19 -47.49,-47.339 -47.49,-47.438 -47.226,-47.701 -47.226,-47.825 -47.325,-47.924 -47.43,-48.029 -47.43,-49.552 -48.268,-50.39 -48.392,-50.39 -48.48,-50.302 J27.5@-48.48,-48.91
ETH2_TXRXB_P: J27.4 U14.24 | length 23.4
  1-TOP w0.15: U14.24@-49.95,-39.2 -50.023,-39.273 -50.023,-42.976 -49.499,-43.5 -44.9,-43.5 -42.8,-45.6 -42.8,-47.1 -43.3,-47.6 -46.5,-47.6 -47.076,-48.176 -47.076,-49.698 -48.121,-50.744 -48.539,-50.744 -48.729,-50.553 -48.853,-50.553 J27.4@-49.75,-51.45
ETH2_TXRXC_N: J27.7 U14.21 | length 21.8
  1-TOP w0.15: v1(-51.9,-45.477) -51.777,-45.6 -50.9,-45.6 -50.799,-45.6 -50.399,-46 -49.327,-46 -49.029,-45.702 -49.029,-45.102 -49.331,-44.8 -50.4,-44.8 -51.377,-43.823 -51.377,-39.273 U14.21@-51.45,-39.2
  8-BOTTOM w0.15: v1(-51.9,-45.477) -51.9,-45.5 -51.8,-45.6 -47.8,-45.6 -47.044,-46.356 -47.044,-46.675 -47.044,-47.047 -46.956,-47.135 -46.847,-47.135 -46.777,-47.205 -46.777,-47.415 -46.847,-47.485 -46.956,-47.485 -47.044,-47.573 -47.044,-47.998 -47.044,-49.714 -46.956,-49.802 -46.832,-49.802 J27.7@-45.94,-48.91
ETH2_TXRXC_P: J27.6 U14.22 | length 21.7
  1-TOP w0.15: v1(-51.9,-46.077) -51.777,-45.954 -50.946,-45.954 -50.546,-46.354 -49.18,-46.354 -48.675,-45.849 -48.675,-44.955 -49.184,-44.446 -50.253,-44.446 -51.023,-43.676 -51.023,-39.273 U14.22@-50.95,-39.2
  8-BOTTOM w0.15: v1(-51.9,-46.077) -51.9,-46.054 -51.8,-45.954 -47.947,-45.954 -47.398,-46.503 -47.398,-49.861 -47.121,-50.138 J27.6@-47.121,-51.361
